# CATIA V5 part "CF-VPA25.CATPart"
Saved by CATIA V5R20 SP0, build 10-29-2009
Part number: CF-VPA25
Bounding box of the stored display mesh (mm): x 0 to 56, y -12.5 to 12.5, z -12.5 to 12.5
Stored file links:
  C:\Users\Utente\Desktop\IO LAVORO\3D X SITO CF\X SITO\PLASTICA\CF-VPA\CF-VPA25.CATPart
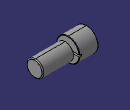
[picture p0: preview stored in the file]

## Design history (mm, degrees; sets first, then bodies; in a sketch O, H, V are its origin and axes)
Set1
  DatumSurface1 to DatumSurface30 "CF-VPA25"
Body1 (main body)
